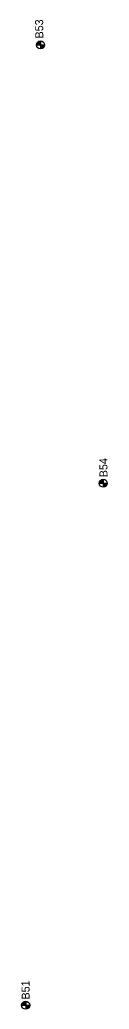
# Model space of a CAD drawing. Extents: x 345549 to 379569, y 127949 to 230467.
# Drawn here: x 360167 to 360274, y 158127 to 159364 of the extents above; entities that cross this region are included whole.
import ezdxf

# ---------------------------------------------------------------- set-up
doc = ezdxf.new("R2010")
doc.units = 0
for name, color, linetype in [('E_SOIL_BORE1 [KAPUR_CADDS_LEVELS]', 7, 'Continuous'), ('E_SOIL_BORE2 [KAPUR_CADDS_LEVELS]', 7, 'Continuous'), ('P_MARK', 7, 'Continuous')]:
    doc.layers.add(name, color=color, linetype=linetype)

msp = doc.modelspace()

# ---------------------------------------------------------------- linework, layer by layer
at = {"layer": 'P_MARK'}
for p, q in [((360185.4, 159332.2), (360195.4, 159332.2)), ((360190.4, 159337.2), (360190.4, 159327.2)), ((360268.6, 158789.4), (360268.6, 158779.4)), ((360263.6, 158784.4), (360273.6, 158784.4)), ((360166.9, 158132), (360176.9, 158132)), ((360171.9, 158137), (360171.9, 158127))]:
    msp.add_line(p, q, dxfattribs=at)
for centre in [(360190.4, 159332.2), (360268.6, 158784.4), (360171.9, 158132)]:
    msp.add_circle(centre, 5, dxfattribs=at)
for centre, radius, start, end in [((360190.4, 159332.2), 4.5, 89.9869, 179.9869), ((360190.4, 159332.2), 4, 89.9869, 179.9869), ((360190.4, 159332.2), 3.5, 89.9869, 179.9869), ((360190.4, 159332.2), 3, 89.9869, 179.9869), ((360190.4, 159332.2), 2.5, 89.9869, 179.9869), ((360190.4, 159332.2), 2, 89.9869, 179.9869), ((360190.4, 159332.2), 1.5, 89.9869, 179.9869), ((360190.4, 159332.2), 1, 89.9869, 179.9869), ((360190.4, 159332.2), 0.5, 89.9869, 179.9869), ((360190.4, 159332.2), 4.5, 269.9869, 359.9869), ((360190.4, 159332.2), 4, 269.9869, 359.9869), ((360190.4, 159332.2), 3.5, 269.9869, 359.9869), ((360190.4, 159332.2), 3, 269.9869, 359.9869), ((360190.4, 159332.2), 2.5, 269.9869, 359.9869), ((360190.4, 159332.2), 2, 269.9869, 359.9869), ((360190.4, 159332.2), 1.5, 269.9869, 359.9869), ((360190.4, 159332.2), 1, 269.9869, 359.9869), ((360190.4, 159332.2), 0.5, 269.9869, 359.9869), ((360268.6, 158784.4), 4.5, 89.9869, 179.9869), ((360268.6, 158784.4), 4, 89.9869, 179.9869), ((360268.6, 158784.4), 3.5, 89.9869, 179.9869), ((360268.6, 158784.4), 3, 89.9869, 179.9869), ((360268.6, 158784.4), 2.5, 89.9869, 179.9869), ((360268.6, 158784.4), 2, 89.9869, 179.9869), ((360268.6, 158784.4), 1.5, 89.9869, 179.9869), ((360268.6, 158784.4), 1, 89.9869, 179.9869), ((360268.6, 158784.4), 0.5, 89.9869, 179.9869), ((360268.6, 158784.4), 4.5, 269.9869, 359.9869), ((360268.6, 158784.4), 4, 269.9869, 359.9869), ((360268.6, 158784.4), 3.5, 269.9869, 359.9869), ((360268.6, 158784.4), 3, 269.9869, 359.9869), ((360268.6, 158784.4), 2.5, 269.9869, 359.9869), ((360268.6, 158784.4), 2, 269.9869, 359.9869), ((360268.6, 158784.4), 1.5, 269.9869, 359.9869), ((360268.6, 158784.4), 1, 269.9869, 359.9869), ((360268.6, 158784.4), 0.5, 269.9869, 359.9869), ((360171.9, 158132), 4.5, 89.9869, 179.9869), ((360171.9, 158132), 4, 89.9869, 179.9869), ((360171.9, 158132), 3.5, 89.9869, 179.9869), ((360171.9, 158132), 3, 89.9869, 179.9869), ((360171.9, 158132), 2.5, 89.9869, 179.9869), ((360171.9, 158132), 2, 89.9869, 179.9869), ((360171.9, 158132), 1.5, 89.9869, 179.9869), ((360171.9, 158132), 1, 89.9869, 179.9869), ((360171.9, 158132), 0.5, 89.9869, 179.9869), ((360171.9, 158132), 4.5, 269.9869, 359.9869), ((360171.9, 158132), 4, 269.9869, 359.9869), ((360171.9, 158132), 3.5, 269.9869, 359.9869), ((360171.9, 158132), 3, 269.9869, 359.9869), ((360171.9, 158132), 2.5, 269.9869, 359.9869), ((360171.9, 158132), 2, 269.9869, 359.9869), ((360171.9, 158132), 1.5, 269.9869, 359.9869), ((360171.9, 158132), 1, 269.9869, 359.9869), ((360171.9, 158132), 0.5, 269.9869, 359.9869)]:
    msp.add_arc(centre, radius, start, end, dxfattribs=at)

# ---------------------------------------------------------------- texts
at = {"layer": 'E_SOIL_BORE1 [KAPUR_CADDS_LEVELS]'}
for s, p in [('B53', (360193.9, 159340.4)), ('B54', (360273.9, 158792))]:
    msp.add_text(s, height=10, rotation=90.6368, dxfattribs=at).set_placement(p)
at = {"layer": 'E_SOIL_BORE2 [KAPUR_CADDS_LEVELS]'}
msp.add_text('B51', height=10, rotation=90.6368, dxfattribs=at).set_placement((360176.9, 158139.2))

doc.saveas('drawing.dxf')
